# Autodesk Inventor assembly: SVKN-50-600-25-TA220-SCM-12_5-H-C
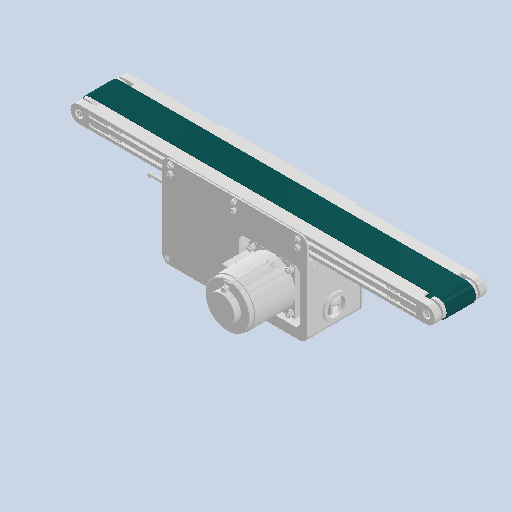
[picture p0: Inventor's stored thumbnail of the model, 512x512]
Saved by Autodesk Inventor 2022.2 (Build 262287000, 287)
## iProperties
Created: 2024-10
Part Number: SVKN-50-600-25-TA220-SCM-12_5-H-C
Document SubType Name: Assembly
Designer: 18907419
Author: 18907419
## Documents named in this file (9)
- C:\Users\18907419\Desktop\automazione\nastro\SVKN-50-600-25-TA220-SCM-12_5-H-C.iam
- C:\Users\18907419\Desktop\automazione\nastro\SVKN-50-600-25_l.ipt
- C:\Users\18907419\Desktop\automazione\nastro\SVKN-50-600-25-H_b.ipt
- C:\Users\18907419\Desktop\automazione\nastro\SVKN-50-25-TA220-SCM-12_5-C_mc.ipt
- C:\Users\18907419\Desktop\automazione\nastro\SVKN25-TA220-SCM-12_5-C-1.ipt
- C:\Users\18907419\Desktop\automazione\nastro\CVS_bolt5-65.ipt
- C:\Users\18907419\Desktop\automazione\nastro\MOTOR25_w.ipt
- C:\Users\18907419\Desktop\automazione\nastro\MOTOR25_n.ipt
- C:\Users\18907419\Desktop\automazione\nastro\CVS__Nut-M5.ipt
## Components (32 placed, 8 different names)
1. SVKN-50-600-25_l
2. SVKN-50-600-25-H_b
3. SVKN-50-25-TA220-SCM-12_5-C_mc
4. SVKN25-TA220-SCM-12_5-C-1
5. CVS_bolt5-65
6. CVS_bolt5-65:1
7. CVS_bolt5-65:2
8. CVS_bolt5-65:3
9. MOTOR25_w
10. MOTOR25_w:1
11. MOTOR25_w:2
12. MOTOR25_w:3
13. MOTOR25_n
14. MOTOR25_n:1
15. MOTOR25_n:2
16. MOTOR25_n:3
17. CVS__Nut-M5
18. CVS__Nut-M5:1
19. CVS__Nut-M5:2
20. CVS__Nut-M5:3
21. CVS__Nut-M5:4
22. CVS__Nut-M5:5
23. CVS__Nut-M5:6
24. CVS__Nut-M5:7
25. CVS__Nut-M5:8
26. CVS__Nut-M5:9
27. CVS__Nut-M5:10
28. CVS__Nut-M5:11
29. CVS__Nut-M5:12
30. CVS__Nut-M5:13
31. CVS__Nut-M5:14
32. CVS__Nut-M5:15
